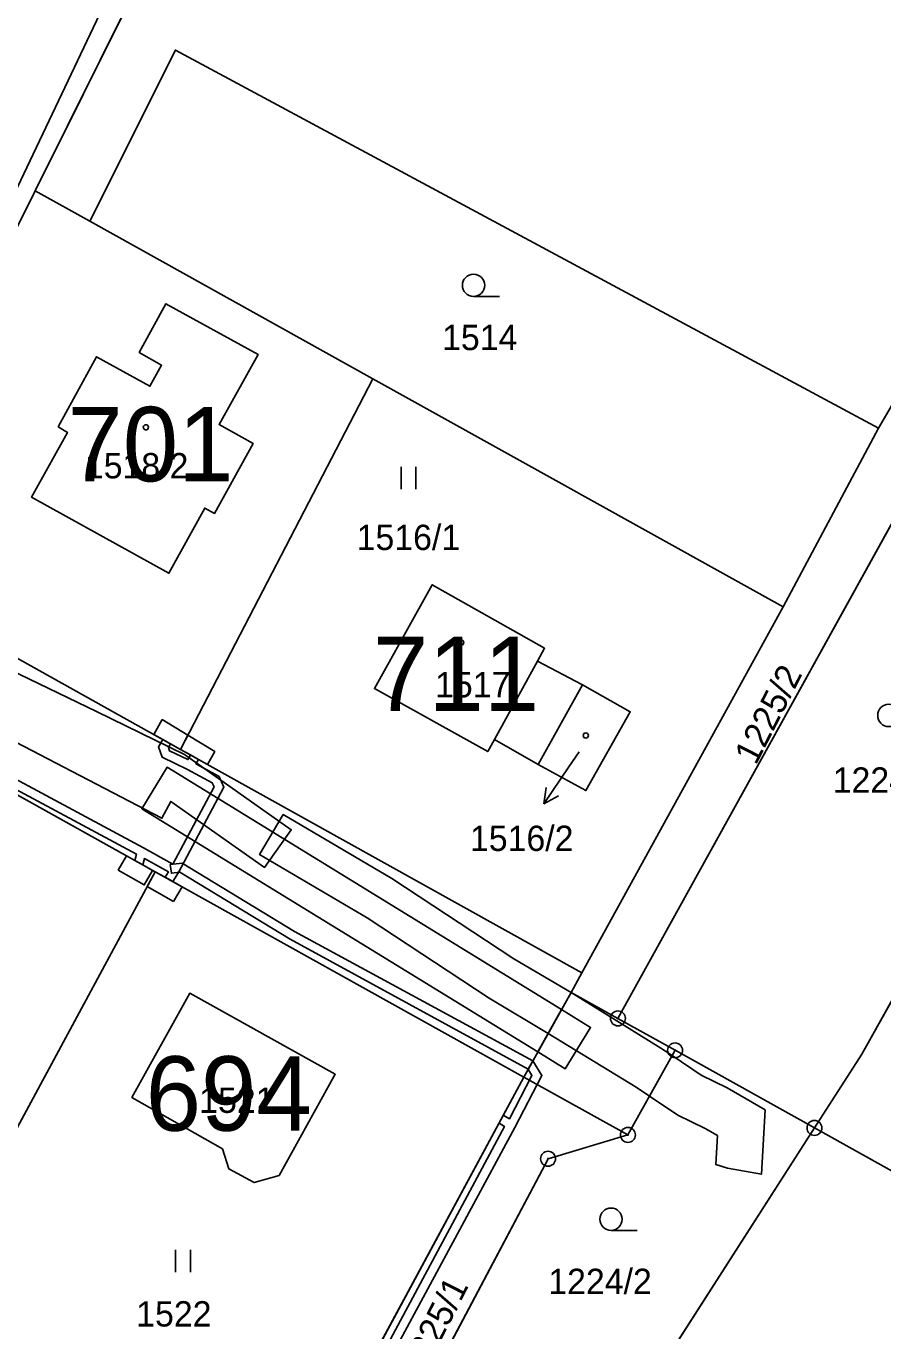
# Model space of a CAD drawing. Extents: x -689422 to -685210, y -987725 to -982160.
# Drawn here: x -687647.2 to -687589.7, y -985251.4 to -985163.8 of the extents above; entities that cross this region are included whole.
import ezdxf

# ---------------------------------------------------------------- set-up
doc = ezdxf.new("R2010")
doc.units = 0
for name, color, linetype in [('KN_Budovy', 7, 'Continuous'), ('KN_Budovy_cisla_domovni', 7, 'Continuous'), ('KN_Hranice_parcel', 7, 'Continuous'), ('KN_Hranice_parcel_vnitrni_kresba', 7, 'Continuous'), ('KN_Parcelni cisla', 7, 'Continuous'), ('KN_Parcelni cisla_sipky', 7, 'Continuous'), ('KN_Polygon parcely', 7, 'Continuous'), ('KN_Popisy_pomistni nazvy nazvy ulic', 7, 'Continuous'), ('KN_POZEMKY_ORNA PUDA', 7, 'Continuous'), ('KN_POZEMKY_OSTATNI PLOCHA', 7, 'Continuous'), ('KN_POZEMKY_TTP', 7, 'Continuous'), ('KN_POZEMKY_ZAHRADA', 7, 'Continuous'), ('KN_POZEMKY_ZASTAVENA PLOCHA', 7, 'Continuous'), ('KN_VYUZITI_17_ostatni plocha_ostatni komunikace', 7, 'Continuous'), ('KN_Věcná břemena k části', 7, 'Continuous'), ('KN_Značky bodu BP', 7, 'Continuous'), ('KN_Značky budov', 7, 'Continuous'), ('KN_Značky kultur', 7, 'Continuous')]:
    doc.layers.add(name, color=color, linetype=linetype)

msp = doc.modelspace()

# ---------------------------------------------------------------- linework, layer by layer
at = {"layer": 'KN_Budovy'}
for points in [[(-687642.48, -985186.01), (-687645.06, -985190.71), (-687644.44, -985191.09), (-687646.85, -985195.43), (-687637.62, -985200.55), (-687635.22, -985196.17), (-687634.56, -985196.53), (-687631.97, -985191.83), (-687634.25, -985190.57), (-687631.64, -985185.86), (-687637.82, -985182.46), (-687639.62, -985185.72), (-687638.12, -985186.59), (-687638.9, -985187.99)], [(-687612.39, -985205.58), (-687619.94, -985201.32), (-687623.82, -985208.29), (-687616.21, -985212.52), (-687615.76, -985211.71), (-687612.87, -985206.44)], [(-687609.62, -985215.14), (-687606.64, -985209.84), (-687609.85, -985208.04), (-687612.82, -985213.39)], [(-687640.11, -985235.73), (-687634.02, -985239.19), (-687633.61, -985240.53), (-687631.89, -985241.45), (-687630.22, -985240.98), (-687626.45, -985234.18), (-687636.22, -985228.74)]]:
    msp.add_lwpolyline(points, close=True, dxfattribs=at)
at = {"layer": 'KN_Hranice_parcel'}
for p, q in [((-687646.61, -985174.88), (-687642.94, -985176.92)), ((-687642.94, -985176.92), (-687623.92, -985187.5)), ((-687589.98, -985190.81), (-687585.86, -985183.75)), ((-687582.61, -985185.51), (-687607.47, -985230.43)), ((-687636.84, -985212.37), (-687623.92, -985187.5)), ((-687623.92, -985187.5), (-687596.37, -985202.8)), ((-687596.37, -985202.8), (-687589.98, -985190.81)), ((-687568.81, -985192.98), (-687591.1, -985232.84)), ((-687609.89, -985227.37), (-687596.37, -985202.8)), ((-687615.76, -985211.71), (-687612.87, -985206.44)), ((-687609.89, -985227.37), (-687636.84, -985212.37)), ((-687638.55, -985220.58), (-687655.11, -985251.26)), ((-687638.55, -985220.58), (-687613.79, -985234.37)), ((-687610.62, -985228.68), (-687609.89, -985227.37)), ((-687613.79, -985234.37), (-687610.62, -985228.68)), ((-687607.47, -985230.43), (-687610.62, -985228.68)), ((-687607.47, -985230.43), (-687603.63, -985232.57)), ((-687594.27, -985237.78), (-687603.63, -985232.57)), ((-687591.1, -985232.84), (-687594.27, -985237.78)), ((-687630.37, -985265.09), (-687613.79, -985234.37)), ((-687594.27, -985237.78), (-687607.59, -985258.53))]:
    msp.add_line(p, q, dxfattribs=at)
for points in [[(-687616.34, -985132.13), (-687627.03, -985135.54), (-687646.61, -985174.88)], [(-687642.94, -985176.92), (-687637.19, -985165.43), (-687589.98, -985190.81)], [(-687636.84, -985212.37), (-687654.88, -985202.31), (-687656.9, -985195.55), (-687646.61, -985174.88)], [(-687631.64, -985185.86), (-687634.25, -985190.57), (-687631.97, -985191.83), (-687634.56, -985196.53), (-687635.22, -985196.17), (-687637.62, -985200.55), (-687646.85, -985195.43), (-687644.44, -985191.09), (-687645.06, -985190.71), (-687642.48, -985186.01), (-687638.9, -985187.99), (-687638.12, -985186.59), (-687639.62, -985185.72), (-687637.82, -985182.46), (-687631.64, -985185.86)], [(-687612.87, -985206.44), (-687612.39, -985205.58), (-687619.94, -985201.32), (-687623.82, -985208.29), (-687616.21, -985212.52), (-687615.76, -985211.71)], [(-687612.87, -985206.44), (-687609.85, -985208.04), (-687606.64, -985209.84), (-687609.62, -985215.14), (-687612.82, -985213.39), (-687615.76, -985211.71)], [(-687665.95, -985214.02), (-687664.37, -985210.76), (-687659.19, -985209.09), (-687638.55, -985220.58)], [(-687631.89, -985241.45), (-687630.22, -985240.98), (-687626.45, -985234.18), (-687636.22, -985228.74), (-687640.11, -985235.73), (-687634.02, -985239.19), (-687633.61, -985240.53), (-687631.89, -985241.45)], [(-687603.63, -985232.57), (-687606.8, -985238.25), (-687612.16, -985239.85), (-687625.76, -985265.53)], [(-687566.32, -985253.35), (-687568.94, -985251.89), (-687594.27, -985237.78)]]:
    msp.add_lwpolyline(points, dxfattribs=at)
at = {"layer": 'KN_Hranice_parcel_vnitrni_kresba'}
msp.add_line((-687609.85, -985208.04), (-687612.82, -985213.39), dxfattribs=at)
at = {"layer": 'KN_Parcelni cisla_sipky'}
for p, q in [((-687610.07, -985212.53), (-687610.76, -985213.54)), ((-687610.76, -985213.54), (-687612.438, -985216.028)), ((-687612.438, -985216.028), (-687612.293, -985214.918)), ((-687612.438, -985216.028), (-687611.463, -985215.478))]:
    msp.add_line(p, q, dxfattribs=at)
at = {"layer": 'KN_Polygon parcely'}
msp.add_lwpolyline([(-687691.94, -985182.32), (-687669.9, -985203.12), (-687671.26, -985211.45), (-687665.95, -985214.02), (-687664.37, -985210.76), (-687659.19, -985209.09), (-687638.55, -985220.58), (-687613.79, -985234.37), (-687610.62, -985228.68), (-687609.89, -985227.37), (-687636.84, -985212.37), (-687654.88, -985202.31), (-687656.9, -985195.55), (-687646.61, -985174.88), (-687627.03, -985135.54), (-687616.34, -985132.13), (-687636.95, -985120.57), (-687633.72, -985131.28), (-687643.61, -985151.16), (-687654.33, -985172.7), (-687662.99, -985190.1), (-687670.63, -985191.49), (-687689.84, -985173.3)], dxfattribs=at)
for points in [[(-687627.03, -985135.54), (-687646.61, -985174.88), (-687642.94, -985176.92), (-687637.19, -985165.43), (-687589.98, -985190.81), (-687585.86, -985183.75), (-687570.88, -985154.81), (-687596.16, -985141.26), (-687616.34, -985132.13)], [(-687568.81, -985192.98), (-687591.1, -985232.84), (-687594.27, -985237.78), (-687568.94, -985251.89), (-687566.32, -985253.35), (-687565.55, -985252.06), (-687522.02, -985179.85), (-687553.2, -985164.2), (-687555.49, -985168.48), (-687559.81, -985176.5), (-687558.72, -985177.3)], [(-687596.37, -985202.8), (-687589.98, -985190.81), (-687637.19, -985165.43), (-687642.94, -985176.92), (-687623.92, -985187.5)], [(-687636.84, -985212.37), (-687623.92, -985187.5), (-687642.94, -985176.92), (-687646.61, -985174.88), (-687656.9, -985195.55), (-687654.88, -985202.31)], [(-687631.64, -985185.86), (-687634.25, -985190.57), (-687631.97, -985191.83), (-687634.56, -985196.53), (-687635.22, -985196.17), (-687637.62, -985200.55), (-687646.85, -985195.43), (-687644.44, -985191.09), (-687645.06, -985190.71), (-687642.48, -985186.01), (-687638.9, -985187.99), (-687638.12, -985186.59), (-687639.62, -985185.72), (-687637.82, -985182.46)], [(-687631.64, -985185.86), (-687637.82, -985182.46), (-687639.62, -985185.72), (-687638.12, -985186.59), (-687638.9, -985187.99), (-687642.48, -985186.01), (-687645.06, -985190.71), (-687644.44, -985191.09), (-687646.85, -985195.43), (-687637.62, -985200.55), (-687635.22, -985196.17), (-687634.56, -985196.53), (-687631.97, -985191.83), (-687634.25, -985190.57)], [(-687582.61, -985185.51), (-687585.86, -985183.75), (-687589.98, -985190.81), (-687596.37, -985202.8), (-687609.89, -985227.37), (-687610.62, -985228.68), (-687607.47, -985230.43)], [(-687607.47, -985230.43), (-687603.63, -985232.57), (-687594.27, -985237.78), (-687591.1, -985232.84), (-687568.81, -985192.98), (-687582.61, -985185.51)], [(-687596.37, -985202.8), (-687623.92, -985187.5), (-687636.84, -985212.37), (-687609.89, -985227.37)], [(-687612.82, -985213.39), (-687615.76, -985211.71), (-687616.21, -985212.52), (-687623.82, -985208.29), (-687619.94, -985201.32), (-687612.39, -985205.58), (-687612.87, -985206.44), (-687609.85, -985208.04), (-687606.64, -985209.84), (-687609.62, -985215.14)], [(-687623.82, -985208.29), (-687616.21, -985212.52), (-687615.76, -985211.71), (-687612.87, -985206.44), (-687612.39, -985205.58), (-687619.94, -985201.32)], [(-687612.87, -985206.44), (-687615.76, -985211.71), (-687612.82, -985213.39), (-687609.62, -985215.14), (-687606.64, -985209.84), (-687609.85, -985208.04)], [(-687665.95, -985214.02), (-687677.81, -985238.56), (-687655.11, -985251.26), (-687638.55, -985220.58), (-687659.19, -985209.09), (-687664.37, -985210.76)], [(-687649.8, -985254.23), (-687630.37, -985265.09), (-687613.79, -985234.37), (-687638.55, -985220.58), (-687655.11, -985251.26)], [(-687631.89, -985241.45), (-687630.22, -985240.98), (-687626.45, -985234.18), (-687636.22, -985228.74), (-687640.11, -985235.73), (-687634.02, -985239.19), (-687633.61, -985240.53)], [(-687631.89, -985241.45), (-687633.61, -985240.53), (-687634.02, -985239.19), (-687640.11, -985235.73), (-687636.22, -985228.74), (-687626.45, -985234.18), (-687630.22, -985240.98)], [(-687630.37, -985265.09), (-687633.36, -985271.14), (-687630.72, -985272.45), (-687629.69, -985272.96), (-687625.76, -985265.53), (-687612.16, -985239.85), (-687606.8, -985238.25), (-687603.63, -985232.57), (-687607.47, -985230.43), (-687610.62, -985228.68), (-687613.79, -985234.37)], [(-687617.66, -985265.17), (-687623.03, -985262.39), (-687618.18, -985252.96), (-687607.59, -985258.53), (-687594.27, -985237.78), (-687603.63, -985232.57), (-687606.8, -985238.25), (-687612.16, -985239.85), (-687625.76, -985265.53), (-687620.88, -985271.54)], [(-687594.27, -985237.78), (-687607.59, -985258.53), (-687600.78, -985262.12), (-687609.42, -985278.66), (-687617.68, -985274.25), (-687618.12, -985274.93), (-687609.91, -985285.02), (-687618.45, -985306.07), (-687602.4, -985317.8), (-687598.98, -985311.08), (-687583.77, -985283.37), (-687569.15, -985258.08), (-687566.32, -985253.35), (-687568.94, -985251.89)]]:
    msp.add_lwpolyline(points, close=True, dxfattribs=at)
at = {"layer": 'KN_POZEMKY_ORNA PUDA'}
for p, q in [((-687591.1, -985232.84), (-687568.81, -985192.98)), ((-687594.27, -985237.78), (-687591.1, -985232.84)), ((-687607.59, -985258.53), (-687594.27, -985237.78)), ((-687568.94, -985251.89), (-687594.27, -985237.78)), ((-687594.27, -985237.78), (-687568.94, -985251.89))]:
    msp.add_line(p, q, dxfattribs=at)
at = {"layer": 'KN_POZEMKY_OSTATNI PLOCHA'}
for p, q in [((-687627.03, -985135.54), (-687646.61, -985174.88)), ((-687646.61, -985174.88), (-687656.9, -985195.55)), ((-687589.98, -985190.81), (-687585.86, -985183.75)), ((-687582.61, -985185.51), (-687607.47, -985230.43)), ((-687596.37, -985202.8), (-687589.98, -985190.81)), ((-687654.88, -985202.31), (-687636.84, -985212.37)), ((-687609.89, -985227.37), (-687596.37, -985202.8)), ((-687638.55, -985220.58), (-687659.19, -985209.09)), ((-687636.84, -985212.37), (-687609.89, -985227.37)), ((-687613.79, -985234.37), (-687638.55, -985220.58)), ((-687609.89, -985227.37), (-687610.62, -985228.68)), ((-687610.62, -985228.68), (-687609.89, -985227.37)), ((-687610.62, -985228.68), (-687613.79, -985234.37)), ((-687613.79, -985234.37), (-687610.62, -985228.68)), ((-687610.62, -985228.68), (-687607.47, -985230.43)), ((-687607.47, -985230.43), (-687610.62, -985228.68)), ((-687607.47, -985230.43), (-687603.63, -985232.57)), ((-687603.63, -985232.57), (-687606.8, -985238.25)), ((-687630.37, -985265.09), (-687613.79, -985234.37)), ((-687606.8, -985238.25), (-687612.16, -985239.85)), ((-687612.16, -985239.85), (-687625.76, -985265.53))]:
    msp.add_line(p, q, dxfattribs=at)
at = {"layer": 'KN_POZEMKY_TTP'}
for p, q in [((-687656.9, -985195.55), (-687646.61, -985174.88)), ((-687646.61, -985174.88), (-687642.94, -985176.92)), ((-687642.94, -985176.92), (-687623.92, -985187.5)), ((-687637.82, -985182.46), (-687639.62, -985185.72)), ((-687631.64, -985185.86), (-687637.82, -985182.46)), ((-687639.62, -985185.72), (-687638.12, -985186.59)), ((-687642.48, -985186.01), (-687645.06, -985190.71)), ((-687638.9, -985187.99), (-687642.48, -985186.01)), ((-687638.12, -985186.59), (-687638.9, -985187.99)), ((-687634.25, -985190.57), (-687631.64, -985185.86)), ((-687636.84, -985212.37), (-687623.92, -985187.5)), ((-687623.92, -985187.5), (-687636.84, -985212.37)), ((-687623.92, -985187.5), (-687596.37, -985202.8)), ((-687644.44, -985191.09), (-687646.85, -985195.43)), ((-687645.06, -985190.71), (-687644.44, -985191.09)), ((-687631.97, -985191.83), (-687634.25, -985190.57)), ((-687634.56, -985196.53), (-687631.97, -985191.83)), ((-687646.85, -985195.43), (-687637.62, -985200.55)), ((-687637.62, -985200.55), (-687635.22, -985196.17)), ((-687635.22, -985196.17), (-687634.56, -985196.53)), ((-687619.94, -985201.32), (-687623.82, -985208.29)), ((-687612.39, -985205.58), (-687619.94, -985201.32)), ((-687636.84, -985212.37), (-687654.88, -985202.31)), ((-687596.37, -985202.8), (-687609.89, -985227.37)), ((-687612.87, -985206.44), (-687612.39, -985205.58)), ((-687609.85, -985208.04), (-687612.87, -985206.44)), ((-687623.82, -985208.29), (-687616.21, -985212.52)), ((-687606.64, -985209.84), (-687609.85, -985208.04)), ((-687659.19, -985209.09), (-687638.55, -985220.58)), ((-687609.62, -985215.14), (-687606.64, -985209.84)), ((-687616.21, -985212.52), (-687615.76, -985211.71)), ((-687615.76, -985211.71), (-687612.82, -985213.39)), ((-687609.89, -985227.37), (-687636.84, -985212.37)), ((-687612.82, -985213.39), (-687609.62, -985215.14)), ((-687638.55, -985220.58), (-687655.11, -985251.26)), ((-687655.11, -985251.26), (-687638.55, -985220.58)), ((-687638.55, -985220.58), (-687613.79, -985234.37)), ((-687636.22, -985228.74), (-687640.11, -985235.73)), ((-687626.45, -985234.18), (-687636.22, -985228.74)), ((-687613.79, -985234.37), (-687630.37, -985265.09)), ((-687630.22, -985240.98), (-687626.45, -985234.18)), ((-687640.11, -985235.73), (-687634.02, -985239.19)), ((-687634.02, -985239.19), (-687633.61, -985240.53)), ((-687633.61, -985240.53), (-687631.89, -985241.45)), ((-687631.89, -985241.45), (-687630.22, -985240.98))]:
    msp.add_line(p, q, dxfattribs=at)
at = {"layer": 'KN_POZEMKY_ZAHRADA'}
for p, q in [((-687642.94, -985176.92), (-687637.19, -985165.43)), ((-687637.19, -985165.43), (-687589.98, -985190.81)), ((-687623.92, -985187.5), (-687642.94, -985176.92)), ((-687607.47, -985230.43), (-687582.61, -985185.51)), ((-687596.37, -985202.8), (-687623.92, -985187.5)), ((-687589.98, -985190.81), (-687596.37, -985202.8)), ((-687568.81, -985192.98), (-687591.1, -985232.84)), ((-687603.63, -985232.57), (-687607.47, -985230.43)), ((-687606.8, -985238.25), (-687603.63, -985232.57)), ((-687594.27, -985237.78), (-687603.63, -985232.57)), ((-687603.63, -985232.57), (-687594.27, -985237.78)), ((-687591.1, -985232.84), (-687594.27, -985237.78)), ((-687612.16, -985239.85), (-687606.8, -985238.25)), ((-687594.27, -985237.78), (-687607.59, -985258.53)), ((-687625.76, -985265.53), (-687612.16, -985239.85))]:
    msp.add_line(p, q, dxfattribs=at)
at = {"layer": 'KN_POZEMKY_ZASTAVENA PLOCHA'}
for p, q in [((-687646.61, -985174.88), (-687627.03, -985135.54)), ((-687637.19, -985165.43), (-687642.94, -985176.92)), ((-687589.98, -985190.81), (-687637.19, -985165.43)), ((-687642.94, -985176.92), (-687646.61, -985174.88)), ((-687639.62, -985185.72), (-687637.82, -985182.46)), ((-687637.82, -985182.46), (-687631.64, -985185.86)), ((-687585.86, -985183.75), (-687589.98, -985190.81)), ((-687638.12, -985186.59), (-687639.62, -985185.72)), ((-687645.06, -985190.71), (-687642.48, -985186.01)), ((-687642.48, -985186.01), (-687638.9, -985187.99)), ((-687638.9, -985187.99), (-687638.12, -985186.59)), ((-687631.64, -985185.86), (-687634.25, -985190.57)), ((-687646.85, -985195.43), (-687644.44, -985191.09)), ((-687644.44, -985191.09), (-687645.06, -985190.71)), ((-687634.25, -985190.57), (-687631.97, -985191.83)), ((-687631.97, -985191.83), (-687634.56, -985196.53)), ((-687637.62, -985200.55), (-687646.85, -985195.43)), ((-687635.22, -985196.17), (-687637.62, -985200.55)), ((-687634.56, -985196.53), (-687635.22, -985196.17)), ((-687623.82, -985208.29), (-687619.94, -985201.32)), ((-687619.94, -985201.32), (-687612.39, -985205.58)), ((-687612.39, -985205.58), (-687612.87, -985206.44)), ((-687612.87, -985206.44), (-687615.76, -985211.71)), ((-687615.76, -985211.71), (-687612.87, -985206.44)), ((-687612.87, -985206.44), (-687609.85, -985208.04)), ((-687616.21, -985212.52), (-687623.82, -985208.29)), ((-687609.85, -985208.04), (-687606.64, -985209.84)), ((-687606.64, -985209.84), (-687609.62, -985215.14)), ((-687615.76, -985211.71), (-687616.21, -985212.52)), ((-687612.82, -985213.39), (-687615.76, -985211.71)), ((-687609.62, -985215.14), (-687612.82, -985213.39)), ((-687640.11, -985235.73), (-687636.22, -985228.74)), ((-687636.22, -985228.74), (-687626.45, -985234.18)), ((-687626.45, -985234.18), (-687630.22, -985240.98)), ((-687634.02, -985239.19), (-687640.11, -985235.73)), ((-687633.61, -985240.53), (-687634.02, -985239.19)), ((-687631.89, -985241.45), (-687633.61, -985240.53)), ((-687630.22, -985240.98), (-687631.89, -985241.45))]:
    msp.add_line(p, q, dxfattribs=at)
at = {"layer": 'KN_VYUZITI_17_ostatni plocha_ostatni komunikace'}
for p, q in [((-687627.03, -985135.54), (-687646.61, -985174.88)), ((-687646.61, -985174.88), (-687656.9, -985195.55)), ((-687589.98, -985190.81), (-687585.86, -985183.75)), ((-687582.61, -985185.51), (-687607.47, -985230.43)), ((-687596.37, -985202.8), (-687589.98, -985190.81)), ((-687654.88, -985202.31), (-687636.84, -985212.37)), ((-687609.89, -985227.37), (-687596.37, -985202.8)), ((-687638.55, -985220.58), (-687659.19, -985209.09)), ((-687636.84, -985212.37), (-687609.89, -985227.37)), ((-687613.79, -985234.37), (-687638.55, -985220.58)), ((-687609.89, -985227.37), (-687610.62, -985228.68)), ((-687610.62, -985228.68), (-687609.89, -985227.37)), ((-687610.62, -985228.68), (-687613.79, -985234.37)), ((-687613.79, -985234.37), (-687610.62, -985228.68)), ((-687610.62, -985228.68), (-687607.47, -985230.43)), ((-687607.47, -985230.43), (-687610.62, -985228.68)), ((-687607.47, -985230.43), (-687603.63, -985232.57)), ((-687603.63, -985232.57), (-687606.8, -985238.25)), ((-687630.37, -985265.09), (-687613.79, -985234.37)), ((-687606.8, -985238.25), (-687612.16, -985239.85)), ((-687612.16, -985239.85), (-687625.76, -985265.53))]:
    msp.add_line(p, q, dxfattribs=at)
at = {"layer": 'KN_Věcná břemena k části'}
for points in [[(-687680.08, -985243.26), (-687677.81, -985238.56), (-687665.95, -985214.02), (-687664.37, -985210.76), (-687663.12, -985210.36), (-687660.53, -985205.33), (-687638.09, -985216.99), (-687637.5, -985215.86), (-687631.2, -985220.29), (-687629.41, -985217.76), (-687636.58, -985212.71), (-687642.48, -985209.83), (-687656.09, -985203.27), (-687660.53, -985201.4), (-687640.59, -985159.43)], [(-687650.36, -985213.74), (-687639.81, -985219.4), (-687639.91, -985219.82), (-687639.37, -985220.12), (-687639.27, -985219.7), (-687637.66, -985220.6), (-687637.88, -985220.95), (-687637.35, -985221.25), (-687636.99, -985220.64), (-687633.93, -985214.91), (-687634.25, -985214.19), (-687635.81, -985213.33), (-687635.64, -985213.04), (-687636.17, -985212.74), (-687636.35, -985213.05), (-687637.59, -985212.46), (-687637.66, -985212.25), (-687637.52, -985211.99), (-687638.04, -985211.7), (-687638.32, -985212.19), (-687638.07, -985212.9), (-687636.37, -985213.71), (-687634.71, -985214.61), (-687634.59, -985214.89), (-687637.37, -985220.08), (-687639.33, -985218.98), (-687650.06, -985213.22)]]:
    msp.add_lwpolyline(points, dxfattribs=at)
for points in [[(-687638.64, -985211.37), (-687638.04, -985211.7), (-687637.52, -985211.99), (-687636.84, -985212.37), (-687636.35, -985211.42), (-687638.07, -985210.37)], [(-687636.35, -985211.42), (-687636.84, -985212.37), (-687636.17, -985212.74), (-687635.64, -985213.04), (-687635.03, -985213.38), (-687634.54, -985212.52)], [(-687612.85, -985232.68), (-687611.26, -985229.83), (-687637.75, -985213.57), (-687639.45, -985216.35)], [(-687612.16, -985231.45), (-687610.62, -985228.68), (-687614.45, -985226.44), (-687622.66, -985221.04), (-687629.95, -985216.75), (-687631.53, -985219.43), (-687624.3, -985223.68), (-687616.11, -985229.06)], [(-687641.03, -985220.47), (-687639.28, -985221.47), (-687638.72, -985220.49), (-687639.37, -985220.12), (-687639.91, -985219.82), (-687640.48, -985219.51)], [(-687637.53, -985220.09), (-687637.46, -985220.69), (-687636.88, -985220.62), (-687629.49, -985225.11), (-687613.49, -985233.84), (-687613.18, -985233.27), (-687629.19, -985224.59), (-687636.74, -985220)], [(-687637.31, -985222.59), (-687636.74, -985221.59), (-687637.35, -985221.25), (-687637.88, -985220.95), (-687638.55, -985220.58), (-687639.08, -985221.57)], [(-687606.8, -985238.25), (-687603.63, -985232.57), (-687607.47, -985230.43), (-687610.62, -985228.68), (-687613.79, -985234.37)], [(-687605.34, -985235.64), (-687603.83, -985232.92), (-687604.58, -985232.42), (-687610.62, -985228.68), (-687612.16, -985231.45), (-687606.24, -985235.04)], [(-687611.26, -985229.83), (-687612.85, -985232.68), (-687611.01, -985233.81), (-687609.31, -985231.03)], [(-687603.83, -985232.92), (-687605.34, -985235.64), (-687603.44, -985236.92), (-687601.6, -985237.82), (-687600.79, -985238.29), (-687600.9, -985240.23), (-687600.12, -985240.49), (-687597.83, -985240.89), (-687597.59, -985236.57), (-687600.14, -985235.08), (-687601.88, -985234.23)], [(-687613.18, -985233.27), (-687613.49, -985233.84), (-687613.25, -985234.27), (-687614.76, -985237.18), (-687615.17, -985236.92), (-687615.45, -985237.45), (-687615.09, -985237.68), (-687626.91, -985259.72), (-687631.34, -985268.11), (-687631.97, -985268.33), (-687631.77, -985268.89), (-687630.92, -985268.61), (-687626.38, -985260), (-687614.4, -985237.76), (-687612.57, -985234.25)]]:
    msp.add_lwpolyline(points, close=True, dxfattribs=at)
at = {"layer": 'KN_Značky bodu BP'}
for centre, radius in [((-687607.47, -985230.43), 0.5), ((-687607.47, -985230.43), 0.0303), ((-687603.63, -985232.57), 0.5), ((-687603.63, -985232.57), 0.0303), ((-687594.27, -985237.78), 0.5), ((-687606.8, -985238.25), 0.5), ((-687606.8, -985238.25), 0.0303), ((-687594.27, -985237.78), 0.0303), ((-687612.16, -985239.85), 0.5), ((-687612.16, -985239.85), 0.0303)]:
    msp.add_circle(centre, radius, dxfattribs=at)
at = {"layer": 'KN_Značky budov'}
for centre in [(-687639.167, -985190.749), (-687617.997, -985205.199), (-687609.627, -985211.439), (-687633.037, -985233.359)]:
    msp.add_circle(centre, 0.175, dxfattribs=at)
at = {"layer": 'KN_Značky kultur'}
for p, q in [((-687617.163, -985181.97), (-687615.413, -985181.97)), ((-687622.031, -985194.9), (-687622.031, -985193.4)), ((-687621.03, -985194.9), (-687621.03, -985193.4)), ((-687607.933, -985244.66), (-687606.183, -985244.66)), ((-687637.171, -985247.46), (-687637.171, -985245.96)), ((-687636.17, -985247.46), (-687636.17, -985245.96))]:
    msp.add_line(p, q, dxfattribs=at)
for centre in [(-687617.163, -985181.22), (-687589.273, -985210.09), (-687607.933, -985243.91)]:
    msp.add_circle(centre, 0.75, dxfattribs=at)

# ---------------------------------------------------------------- texts
at = {"layer": 'KN_Budovy_cisla_domovni'}
for s, p in [('701', (-687644.439, -985194.379)), ('711', (-687623.92, -985209.794)), ('694', (-687639.182, -985237.969))]:
    msp.add_text(s, height=5, dxfattribs=at).set_placement(p)
at = {"layer": 'KN_Parcelni cisla'}
for s, p in [('1514', (-687619.28, -985185.57)), ('1518/2', (-687643.267, -985194.18)), ('1516/1', (-687625.017, -985198.99)), ('1517', (-687619.75, -985208.88)), ('1224/1', (-687593.047, -985215.28)), ('1516/2', (-687617.407, -985219.19)), ('1521', (-687635.59, -985236.77)), ('1224/2', (-687612.147, -985248.93)), ('1522', (-687639.82, -985251.11))]:
    msp.add_text(s, height=1.7, dxfattribs=at).set_placement(p)
for s, p in [('1225/2', (-687598.204, -985213.483)), ('1225/1', (-687620.624, -985254.573))]:
    msp.add_text(s, height=1.7, rotation=63, dxfattribs=at).set_placement(p)
at = {"layer": 'KN_Popisy_pomistni nazvy nazvy ulic'}
msp.add_text('±eskodubská', height=7.5, rotation=334, dxfattribs=at).set_placement((-687592.972, -985139.093))

doc.saveas('drawing.dxf')
